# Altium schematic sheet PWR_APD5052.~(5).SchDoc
size A4
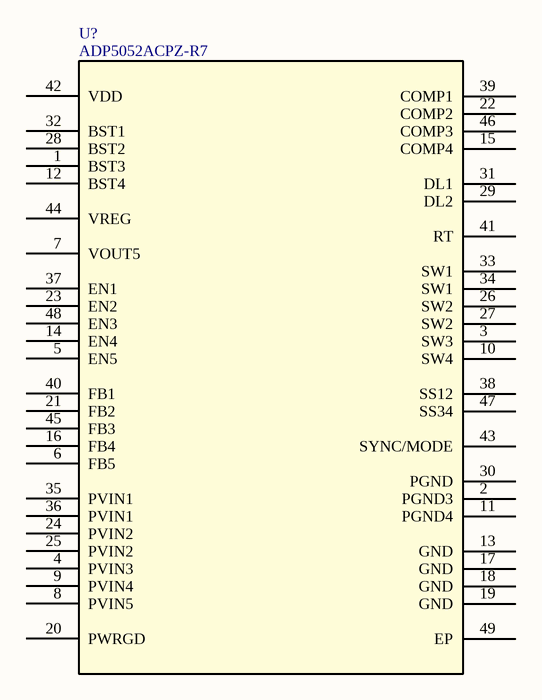
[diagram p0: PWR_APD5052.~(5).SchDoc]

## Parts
U?  ADP5052ACPZ-R7  [CP_48_13]

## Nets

Not connected (* = marked no-connect by the designer): U? 1(BST3) 2(PGND3) 3(SW3) 4(PVIN3) 5(EN5) 6(FB5) 7(VOUT5) 8(PVIN5) 9(PVIN4) 10(SW4) 11(PGND4) 12(BST4) 13(GND) 14(EN4) 15(COMP4) 16(FB4) 17(GND) 18(GND) 19(GND) 20(PWRGD) 21(FB2) 22(COMP2) 23(EN2) 24(PVIN2) 25(PVIN2) 26(SW2) 27(SW2) 28(BST2) 29(DL2) 30(PGND) 31(DL1) 32(BST1) 33(SW1) 34(SW1) 35(PVIN1) 36(PVIN1) 37(EN1) 38(SS12) 39(COMP1) 40(FB1) 41(RT) 42(VDD) 43(SYNC/MODE) 44(VREG) 45(FB3) 46(COMP3) 47(SS34) 48(EN3) 49(EP)

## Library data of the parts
U? = ADP5052ACPZ-R7: Imported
